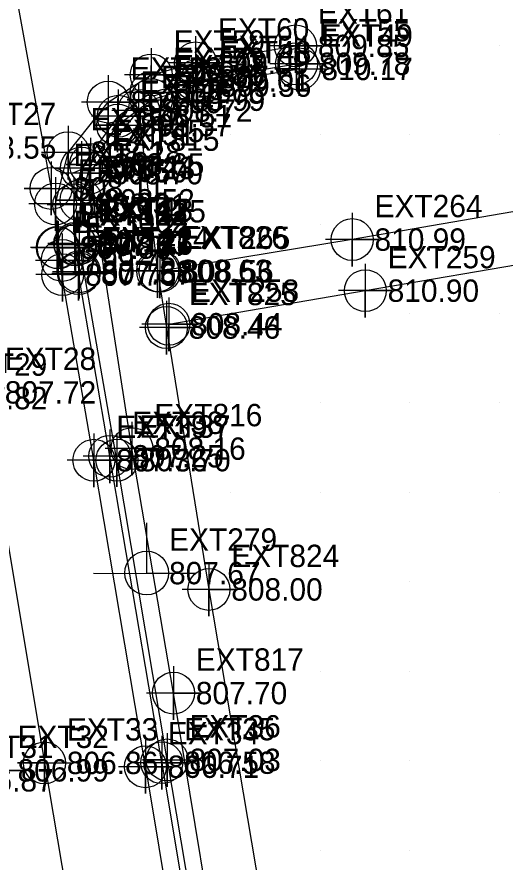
# Model space of a CAD drawing. Extents: x 1762120 to 1766775, y 709485 to 712965.
# Drawn here: x 1763846.1 to 1763900.7, y 712558.7 to 712653.2 of the extents above; entities that cross this region are included whole.
import ezdxf

# ---------------------------------------------------------------- set-up
doc = ezdxf.new("R2010")
doc.units = 0
for name, color, linetype in [('Exist DTM Crownline Cogo Elevation', 7, 'Continuous'), ('Exist DTM Crownline Cogo Number', 7, 'Continuous'), ('Exist DTM Crownline Cogo Point CELL', 7, 'Continuous'), ('Exist DTM Drainline', 7, 'Continuous'), ('Exist DTM Drainline Cogo Elevation', 7, 'Continuous'), ('Exist DTM Drainline Cogo Number', 7, 'Continuous'), ('Exist DTM Drainline Cogo Point CELL', 7, 'Continuous'), ('Exist DTM QL2 LIDAR Elevation Point', 7, 'Continuous'), ('Exist Roads Curbs', 7, 'Continuous'), ('Exist Roads Curbs Cogo Elevation', 7, 'Continuous'), ('Exist Roads Curbs Cogo Number', 7, 'Continuous'), ('Exist Roads Curbs Cogo Point CELL', 7, 'Continuous'), ('Exist Roads EOP', 7, 'Continuous'), ('Exist Roads EOP Cogo Elevation', 7, 'Continuous'), ('Exist Roads EOP Cogo Number', 7, 'Continuous'), ('Exist Roads EOP Cogo Point CELL', 7, 'Continuous'), ('Exist Roads EOP Other', 7, 'Continuous'), ('Exist Roads EOP Other Cogo Elevation', 7, 'Continuous'), ('Exist Roads EOP Other Cogo Number', 7, 'Continuous'), ('Exist Roads EOP Other Cogo Point CELL', 7, 'Continuous'), ('Exist Roads EOT', 7, 'Continuous'), ('Exist Roads EOT Cogo Comment', 7, 'Continuous'), ('Exist Roads EOT Cogo Elevation', 7, 'Continuous'), ('Exist Roads EOT Cogo Number', 7, 'Continuous'), ('Exist Roads EOT Cogo Point CELL', 7, 'Continuous'), ('Exist Structure Minor Drop Inlet', 7, 'Continuous'), ('Exist Structure Minor Drop Inlet Cogo Elevation', 7, 'Continuous'), ('Exist Structure Minor Drop Inlet Cogo Number', 7, 'Continuous'), ('Exist Structure Minor Drop Inlet Cogo Point CELL', 7, 'Continuous'), ('Exist Structure Minor Pipes RCP 15 Inch Cogo Elevation', 7, 'Continuous'), ('Exist Structure Minor Pipes RCP 15 Inch Cogo Number', 7, 'Continuous'), ('Exist Structure Minor Pipes RCP 15 Inch Cogo Point CELL', 7, 'Continuous'), ('Exist Utilities Power Joint Use Telephone CELL', 7, 'Continuous'), ('Exist Utilities Power Joint Use Telephone Cogo Elevation', 7, 'Continuous'), ('Exist Utilities Power Joint Use Telephone Cogo Number', 7, 'Continuous')]:
    doc.layers.add(name, color=color, linetype=linetype)

msp = doc.modelspace()

# ---------------------------------------------------------------- linework, layer by layer
at = {"layer": 'Exist DTM Crownline Cogo Point CELL'}
msp.add_lwpolyline([(1763843.626, 712571.925), (1763843.626, 712565.925), (1763843.626, 712568.925), (1763846.626, 712568.925), (1763840.626, 712568.925)], dxfattribs=at)
at = {"layer": 'Exist DTM Drainline'}
for points in [[(1763852.526, 712627.824), (1763852.422, 712632.146), (1763853.273, 712636.265), (1763857.393, 712642.054), (1763861.051, 712644.706), (1763866.138, 712646.042), (1763877.334, 712647.914)], [(1763862.254, 712569.784), (1763856.449, 712604.035), (1763852.957, 712624.458)], [(1763862.254, 712569.784), (1763865.235, 712551.849), (1763870.388, 712520.524), (1763872.037, 712510.908)]]:
    msp.add_lwpolyline(points, dxfattribs=at)
at = {"layer": 'Exist DTM Drainline Cogo Point CELL'}
for points in [[(1763877.334, 712650.914), (1763877.334, 712644.914), (1763877.334, 712647.914), (1763880.334, 712647.914), (1763874.334, 712647.914)], [(1763866.138, 712649.042), (1763866.138, 712643.042), (1763866.138, 712646.042), (1763869.138, 712646.042), (1763863.138, 712646.042)], [(1763861.051, 712647.706), (1763861.051, 712641.706), (1763861.051, 712644.706), (1763864.051, 712644.706), (1763858.051, 712644.706)], [(1763857.393, 712645.054), (1763857.393, 712639.054), (1763857.393, 712642.054), (1763860.393, 712642.054), (1763854.393, 712642.054)], [(1763853.273, 712639.265), (1763853.273, 712633.265), (1763853.273, 712636.265), (1763856.273, 712636.265), (1763850.273, 712636.265)], [(1763852.422, 712635.146), (1763852.422, 712629.146), (1763852.422, 712632.146), (1763855.422, 712632.146), (1763849.422, 712632.146)], [(1763852.526, 712630.824), (1763852.526, 712624.824), (1763852.526, 712627.824), (1763855.526, 712627.824), (1763849.526, 712627.824)], [(1763852.957, 712627.458), (1763852.957, 712621.458), (1763852.957, 712624.458), (1763855.957, 712624.458), (1763849.957, 712624.458)], [(1763856.449, 712607.035), (1763856.449, 712601.035), (1763856.449, 712604.035), (1763859.449, 712604.035), (1763853.449, 712604.035)], [(1763862.254, 712572.784), (1763862.254, 712566.784), (1763862.254, 712569.784), (1763865.254, 712569.784), (1763859.254, 712569.784)]]:
    msp.add_lwpolyline(points, dxfattribs=at)
for centre in [(1763877.334, 712647.914), (1763866.138, 712646.042), (1763861.051, 712644.706), (1763857.393, 712642.054), (1763853.273, 712636.265), (1763852.422, 712632.146), (1763852.526, 712627.824), (1763852.957, 712624.458), (1763856.449, 712604.035), (1763862.254, 712569.784)]:
    msp.add_circle(centre, 2.344, dxfattribs=at)
at = {"layer": 'Exist DTM QL2 LIDAR Elevation Point'}
for p, q in [((1763900, 712650), (1763900, 712650)), ((1763870, 712640), (1763870, 712640)), ((1763880, 712640), (1763880, 712640)), ((1763890, 712640), (1763890, 712640)), ((1763900, 712640), (1763900, 712640)), ((1763870, 712630), (1763870, 712630)), ((1763880, 712630), (1763880, 712630)), ((1763890, 712620), (1763890, 712620)), ((1763900, 712620), (1763900, 712620)), ((1763870, 712610), (1763870, 712610)), ((1763880, 712610), (1763880, 712610)), ((1763890, 712610), (1763890, 712610)), ((1763900, 712610), (1763900, 712610)), ((1763870, 712600), (1763870, 712600)), ((1763880, 712600), (1763880, 712600)), ((1763890, 712600), (1763890, 712600)), ((1763900, 712600), (1763900, 712600)), ((1763870, 712590), (1763870, 712590)), ((1763880, 712590), (1763880, 712590)), ((1763890, 712590), (1763890, 712590)), ((1763880, 712580), (1763880, 712580)), ((1763890, 712580), (1763890, 712580)), ((1763880, 712570), (1763880, 712570)), ((1763890, 712570), (1763890, 712570)), ((1763880, 712560), (1763880, 712560)), ((1763890, 712560), (1763890, 712560))]:
    msp.add_line(p, q, dxfattribs=at)
at = {"layer": 'Exist Roads Curbs'}
for points in [[(1763862.851, 712570.097), (1763857.241, 712603.606), (1763853.036, 712627.819), (1763853.222, 712632.652), (1763854.3, 712636.654), (1763857.323, 712641.052), (1763861.112, 712643.902), (1763866.262, 712645.471), (1763877.624, 712647.337)], [(1763862.851, 712570.097), (1763865.927, 712552.006), (1763871.153, 712520.608), (1763872.734, 712511.007)]]:
    msp.add_lwpolyline(points, dxfattribs=at)
at = {"layer": 'Exist Roads Curbs Cogo Point CELL'}
for points in [[(1763877.624, 712650.337), (1763877.624, 712644.337), (1763877.624, 712647.337), (1763874.894, 712647.337), (1763880.624, 712647.337)], [(1763866.262, 712648.471), (1763866.262, 712642.471), (1763866.262, 712645.471), (1763863.532, 712645.471), (1763869.262, 712645.471)], [(1763861.112, 712646.902), (1763861.112, 712640.902), (1763861.112, 712643.902), (1763858.382, 712643.902), (1763864.112, 712643.902)], [(1763857.323, 712644.052), (1763857.323, 712638.052), (1763857.323, 712641.052), (1763854.593, 712641.052), (1763860.323, 712641.052)], [(1763854.3, 712639.654), (1763854.3, 712633.654), (1763854.3, 712636.654), (1763851.57, 712636.654), (1763857.3, 712636.654)], [(1763853.222, 712635.652), (1763853.222, 712629.652), (1763853.222, 712632.652), (1763850.492, 712632.652), (1763856.222, 712632.652)], [(1763853.036, 712630.819), (1763853.036, 712624.819), (1763853.036, 712627.819), (1763850.306, 712627.819), (1763856.036, 712627.819)], [(1763857.241, 712606.606), (1763857.241, 712600.606), (1763857.241, 712603.606), (1763854.511, 712603.606), (1763860.241, 712603.606)], [(1763862.851, 712573.097), (1763862.851, 712567.097), (1763862.851, 712570.097), (1763860.121, 712570.097), (1763865.851, 712570.097)]]:
    msp.add_lwpolyline(points, dxfattribs=at)
for centre in [(1763877.624, 712647.337), (1763866.262, 712645.471), (1763861.112, 712643.902), (1763857.323, 712641.052), (1763854.3, 712636.654), (1763853.222, 712632.652), (1763853.036, 712627.819), (1763857.241, 712603.606), (1763862.851, 712570.097)]:
    msp.add_circle(centre, 2.344, dxfattribs=at)
at = {"layer": 'Exist Roads EOP'}
for points in [[(1763860.431, 712569.332), (1763854.67, 712603.593), (1763850.574, 712627.378), (1763850.38, 712632.243), (1763851.789, 712637.981), (1763856.271, 712643.636), (1763861.083, 712646.664), (1763866.035, 712648.008), (1763877.217, 712649.913)], [(1763860.431, 712569.332), (1763863.418, 712551.371), (1763868.592, 712520.228), (1763870.179, 712510.62)]]:
    msp.add_lwpolyline(points, dxfattribs=at)
at = {"layer": 'Exist Roads EOP Cogo Point CELL'}
for points in [[(1763877.217, 712652.913), (1763877.217, 712646.913), (1763877.217, 712649.913), (1763880.217, 712649.913), (1763874.217, 712649.913)], [(1763866.035, 712651.008), (1763866.035, 712645.008), (1763866.035, 712648.008), (1763869.035, 712648.008), (1763863.035, 712648.008)], [(1763861.083, 712649.664), (1763861.083, 712643.664), (1763861.083, 712646.664), (1763864.083, 712646.664), (1763858.083, 712646.664)], [(1763856.271, 712646.636), (1763856.271, 712640.636), (1763856.271, 712643.636), (1763859.271, 712643.636), (1763853.271, 712643.636)], [(1763851.789, 712640.981), (1763851.789, 712634.981), (1763851.789, 712637.981), (1763854.789, 712637.981), (1763848.789, 712637.981)], [(1763850.38, 712635.243), (1763850.38, 712629.243), (1763850.38, 712632.243), (1763853.38, 712632.243), (1763847.38, 712632.243)], [(1763850.574, 712630.378), (1763850.574, 712624.378), (1763850.574, 712627.378), (1763853.574, 712627.378), (1763847.574, 712627.378)], [(1763854.67, 712606.593), (1763854.67, 712600.593), (1763854.67, 712603.593), (1763857.67, 712603.593), (1763851.67, 712603.593)], [(1763860.431, 712572.332), (1763860.431, 712566.332), (1763860.431, 712569.332), (1763863.431, 712569.332), (1763857.431, 712569.332)]]:
    msp.add_lwpolyline(points, dxfattribs=at)
for centre in [(1763877.217, 712649.913), (1763866.035, 712648.008), (1763861.083, 712646.664), (1763856.271, 712643.636), (1763851.789, 712637.981), (1763850.38, 712632.243), (1763850.574, 712627.378), (1763854.67, 712603.593), (1763860.431, 712569.332)]:
    msp.add_circle(centre, 2.344, dxfattribs=at)
at = {"layer": 'Exist Roads EOP Other'}
msp.add_lwpolyline([(1763854.132, 712635.686), (1763859.673, 712642.69), (1763861.796, 712624.763), (1763862.778, 712618.431), (1763867.533, 712589.151), (1763873.757, 712552.303), (1763879.823, 712515.119), (1763886.226, 712476.795), (1763880.517, 712475.736), (1763875.337, 712505.878), (1763869.64, 712540.755), (1763863.568, 712577.565), (1763858.925, 712604.892)], close=True, dxfattribs=at)
for points in [[(1763928.955, 712636.103), (1763903.68, 712631.732), (1763883.556, 712628.264), (1763862.046, 712624.714)], [(1763863.043, 712618.801), (1763885.025, 712622.553), (1763905.122, 712625.986), (1763930.142, 712630.358)]]:
    msp.add_lwpolyline(points, dxfattribs=at)
at = {"layer": 'Exist Roads EOP Other Cogo Point CELL'}
for points in [[(1763859.673, 712645.69), (1763859.673, 712639.69), (1763859.673, 712642.69), (1763862.673, 712642.69), (1763856.673, 712642.69)], [(1763854.132, 712638.686), (1763854.132, 712632.686), (1763854.132, 712635.686), (1763857.132, 712635.686), (1763851.132, 712635.686)], [(1763883.556, 712631.264), (1763883.556, 712625.264), (1763883.556, 712628.264), (1763886.556, 712628.264), (1763880.556, 712628.264)], [(1763861.796, 712627.763), (1763861.796, 712621.763), (1763861.796, 712624.763), (1763864.796, 712624.763), (1763858.796, 712624.763)], [(1763862.046, 712627.714), (1763862.046, 712621.714), (1763862.046, 712624.714), (1763865.046, 712624.714), (1763859.046, 712624.714)], [(1763885.025, 712625.553), (1763885.025, 712619.553), (1763885.025, 712622.553), (1763888.025, 712622.553), (1763882.025, 712622.553)], [(1763862.778, 712621.431), (1763862.778, 712615.431), (1763862.778, 712618.431), (1763865.778, 712618.431), (1763859.778, 712618.431)], [(1763863.043, 712621.801), (1763863.043, 712615.801), (1763863.043, 712618.801), (1763866.043, 712618.801), (1763860.043, 712618.801)], [(1763858.925, 712607.892), (1763858.925, 712601.892), (1763858.925, 712604.892), (1763861.925, 712604.892), (1763855.925, 712604.892)], [(1763867.533, 712592.151), (1763867.533, 712586.151), (1763867.533, 712589.151), (1763870.533, 712589.151), (1763864.533, 712589.151)], [(1763863.568, 712580.565), (1763863.568, 712574.565), (1763863.568, 712577.565), (1763866.568, 712577.565), (1763860.568, 712577.565)]]:
    msp.add_lwpolyline(points, dxfattribs=at)
for centre in [(1763859.673, 712642.69), (1763854.132, 712635.686), (1763883.556, 712628.264), (1763861.796, 712624.763), (1763862.046, 712624.714), (1763885.025, 712622.553), (1763862.778, 712618.431), (1763863.043, 712618.801), (1763858.925, 712604.892), (1763867.533, 712589.151), (1763863.568, 712577.565)]:
    msp.add_circle(centre, 2.344, dxfattribs=at)
at = {"layer": 'Exist Roads EOT'}
msp.add_line((1763842.863, 712672.898), (1763849.88, 712633.986), dxfattribs=at)
for points in [[(1763789.832, 712926.884), (1763795.992, 712888.052), (1763800.75, 712859.942), (1763807.254, 712820.955), (1763816.86, 712762.721), (1763822.148, 712731.849), (1763825.695, 712709.767), (1763831.213, 712676.817), (1763837.744, 712638.56), (1763842.2, 712611.183), (1763849.139, 712569.759)], [(1763849.139, 712569.759), (1763854.496, 712537.963), (1763859.372, 712509.363)]]:
    msp.add_lwpolyline(points, dxfattribs=at)
at = {"layer": 'Exist Roads EOT Cogo Point CELL'}
for points in [[(1763849.88, 712636.986), (1763849.88, 712630.986), (1763849.88, 712633.986), (1763846.88, 712633.986), (1763852.88, 712633.986)], [(1763849.139, 712572.759), (1763849.139, 712566.759), (1763849.139, 712569.759), (1763846.139, 712569.759), (1763852.139, 712569.759)]]:
    msp.add_lwpolyline(points, dxfattribs=at)
for centre in [(1763849.88, 712633.986), (1763849.139, 712569.759)]:
    msp.add_circle(centre, 2.344, dxfattribs=at)
at = {"layer": 'Exist Structure Minor Drop Inlet'}
msp.add_lwpolyline([(1763850.681, 712627.337), (1763851.172, 712624.343), (1763853.028, 712624.663), (1763852.61, 712627.677)], dxfattribs=at)
at = {"layer": 'Exist Structure Minor Drop Inlet Cogo Point CELL'}
for points in [[(1763850.681, 712630.337), (1763850.681, 712624.337), (1763850.681, 712627.337), (1763853.681, 712627.337), (1763847.681, 712627.337)], [(1763852.61, 712630.677), (1763852.61, 712624.677), (1763852.61, 712627.677), (1763855.61, 712627.677), (1763849.61, 712627.677)], [(1763851.172, 712627.343), (1763851.172, 712621.343), (1763851.172, 712624.343), (1763854.172, 712624.343), (1763848.172, 712624.343)], [(1763853.028, 712627.663), (1763853.028, 712621.663), (1763853.028, 712624.663), (1763856.028, 712624.663), (1763850.028, 712624.663)]]:
    msp.add_lwpolyline(points, dxfattribs=at)
for centre in [(1763852.61, 712627.677), (1763850.681, 712627.337), (1763853.028, 712624.663), (1763851.172, 712624.343)]:
    msp.add_circle(centre, 2.344, dxfattribs=at)
at = {"layer": 'Exist Structure Minor Pipes RCP 15 Inch Cogo Point CELL'}
msp.add_lwpolyline([(1763851.128, 712628.938), (1763851.128, 712622.938), (1763851.128, 712625.938), (1763854.128, 712625.938), (1763848.128, 712625.938)], dxfattribs=at)
msp.add_circle((1763851.128, 712625.938), 2.344, dxfattribs=at)
at = {"layer": 'Exist Utilities Power Joint Use Telephone CELL'}
msp.add_line((1763860.578, 712590.978), (1763860.578, 712590.978), dxfattribs=at)
msp.add_lwpolyline([(1763854.64, 712590.978), (1763865.978, 712590.94), (1763860.578, 712590.958), (1763860.578, 712596.603)], dxfattribs=at)
msp.add_circle((1763860.579, 712590.984), 2.45, dxfattribs=at)

# ---------------------------------------------------------------- texts
at = {"layer": 'Exist DTM Crownline Cogo Elevation'}
for s, p in [('807.82', (1763839.233, 712609.29)), ('806.99', (1763846.126, 712567.675))]:
    msp.add_text(s, height=2.5, dxfattribs=at).set_placement(p)
at = {"layer": 'Exist DTM Crownline Cogo Number'}
for s, p in [('EXT29', (1763839.233, 712613.04)), ('EXT32', (1763846.126, 712571.425))]:
    msp.add_text(s, height=2.5, dxfattribs=at).set_placement(p)
at = {"layer": 'Exist DTM Drainline Cogo Elevation'}
for s, p in [('809.78', (1763879.834, 712646.664)), ('809.01', (1763868.638, 712644.792)), ('808.75', (1763863.551, 712643.456)), ('808.51', (1763859.893, 712640.804)), ('808.23', (1763855.773, 712635.015)), ('808.01', (1763854.922, 712630.896)), ('807.63', (1763855.026, 712626.574)), ('807.57', (1763855.457, 712623.208)), ('807.25', (1763858.949, 712602.785)), ('806.58', (1763864.754, 712568.534))]:
    msp.add_text(s, height=2.5, dxfattribs=at).set_placement(p)
at = {"layer": 'Exist DTM Drainline Cogo Number'}
for s, p in [('EXT55', (1763879.834, 712650.414)), ('EXT54', (1763868.638, 712648.542)), ('EXT53', (1763863.551, 712647.206)), ('EXT52', (1763859.893, 712644.554)), ('EXT51', (1763855.773, 712638.765)), ('EXT50', (1763854.922, 712634.646)), ('EXT42', (1763855.026, 712630.324)), ('EXT41', (1763855.457, 712626.958)), ('EXT38', (1763858.949, 712606.535)), ('EXT35', (1763864.754, 712572.284))]:
    msp.add_text(s, height=2.5, dxfattribs=at).set_placement(p)
at = {"layer": 'Exist Roads Curbs Cogo Elevation'}
for s, p in [('810.17', (1763880.124, 712646.087)), ('809.36', (1763868.762, 712644.221)), ('808.99', (1763863.612, 712642.652)), ('808.57', (1763859.823, 712639.802)), ('808.65', (1763856.8, 712635.404)), ('808.52', (1763855.722, 712631.402)), ('808.26', (1763855.536, 712626.569)), ('807.70', (1763859.741, 712602.356)), ('807.03', (1763865.351, 712568.847))]:
    msp.add_text(s, height=2.5, dxfattribs=at).set_placement(p)
at = {"layer": 'Exist Roads Curbs Cogo Number'}
for s, p in [('EXT49', (1763880.124, 712649.837)), ('EXT48', (1763868.762, 712647.971)), ('EXT47', (1763863.612, 712646.402)), ('EXT46', (1763859.823, 712643.552)), ('EXT45', (1763856.8, 712639.154)), ('EXT44', (1763855.722, 712635.152)), ('EXT43', (1763855.536, 712630.319)), ('EXT37', (1763859.741, 712606.106)), ('EXT36', (1763865.351, 712572.597))]:
    msp.add_text(s, height=2.5, dxfattribs=at).set_placement(p)
at = {"layer": 'Exist Roads EOP Cogo Elevation'}
for s, p in [('809.85', (1763879.717, 712648.663)), ('809.09', (1763868.535, 712646.758)), ('808.86', (1763863.583, 712645.414)), ('808.50', (1763858.771, 712642.386)), ('808.18', (1763854.289, 712636.731)), ('808.03', (1763852.88, 712630.993)), ('807.87', (1763853.074, 712626.128)), ('807.36', (1763857.17, 712602.343)), ('806.71', (1763862.931, 712568.082))]:
    msp.add_text(s, height=2.5, dxfattribs=at).set_placement(p)
at = {"layer": 'Exist Roads EOP Cogo Number'}
for s, p in [('EXT61', (1763879.717, 712652.413)), ('EXT60', (1763868.535, 712650.508)), ('EXT59', (1763863.583, 712649.164)), ('EXT58', (1763858.771, 712646.136)), ('EXT57', (1763854.289, 712640.481)), ('EXT56', (1763852.88, 712634.743)), ('EXT40', (1763853.074, 712629.878)), ('EXT39', (1763857.17, 712606.093)), ('EXT34', (1763862.931, 712571.832))]:
    msp.add_text(s, height=2.5, dxfattribs=at).set_placement(p)
at = {"layer": 'Exist Roads EOP Other Cogo Elevation'}
for s, p in [('808.72', (1763862.173, 712641.44)), ('808.70', (1763856.632, 712634.436)), ('810.99', (1763886.056, 712627.014)), ('808.63', (1763864.296, 712623.513)), ('808.56', (1763864.546, 712623.464)), ('810.90', (1763887.525, 712621.303)), ('808.46', (1763865.278, 712617.181)), ('808.44', (1763865.543, 712617.551)), ('808.16', (1763861.425, 712603.642)), ('808.00', (1763870.033, 712587.901)), ('807.70', (1763866.068, 712576.315))]:
    msp.add_text(s, height=2.5, dxfattribs=at).set_placement(p)
at = {"layer": 'Exist Roads EOP Other Cogo Number'}
for s, p in [('EXT827', (1763862.173, 712645.19)), ('EXT815', (1763856.632, 712638.186)), ('EXT264', (1763886.056, 712630.764)), ('EXT826', (1763864.296, 712627.263)), ('EXT265', (1763864.546, 712627.214)), ('EXT259', (1763887.525, 712625.053)), ('EXT825', (1763865.278, 712620.931)), ('EXT258', (1763865.543, 712621.301)), ('EXT816', (1763861.425, 712607.392)), ('EXT824', (1763870.033, 712591.651)), ('EXT817', (1763866.068, 712580.065))]:
    msp.add_text(s, height=2.5, dxfattribs=at).set_placement(p)
at = {"layer": 'Exist Roads EOT Cogo Comment'}
msp.add_text('BL*3002', height=2.5, dxfattribs=at).set_placement((1763852.38, 712628.986))
at = {"layer": 'Exist Roads EOT Cogo Elevation'}
for s, p in [('808.55', (1763840.244, 712637.31)), ('808.11', (1763852.38, 712632.736)), ('807.72', (1763844.7, 712609.933)), ('806.86', (1763851.639, 712568.509)), ('806.87', (1763839.941, 712566.56))]:
    msp.add_text(s, height=2.5, dxfattribs=at).set_placement(p)
at = {"layer": 'Exist Roads EOT Cogo Number'}
for s, p in [('EXT27', (1763840.244, 712641.06)), ('EXT62', (1763852.38, 712636.486)), ('EXT28', (1763844.7, 712613.683)), ('EXT33', (1763851.639, 712572.259)), ('EXT31', (1763839.941, 712570.31))]:
    msp.add_text(s, height=2.5, dxfattribs=at).set_placement(p)
at = {"layer": 'Exist Structure Minor Drop Inlet Cogo Elevation'}
for s, p in [('807.57', (1763855.11, 712626.427)), ('807.79', (1763853.181, 712626.087)), ('807.76', (1763853.672, 712623.093)), ('807.58', (1763855.528, 712623.413))]:
    msp.add_text(s, height=2.5, dxfattribs=at).set_placement(p)
at = {"layer": 'Exist Structure Minor Drop Inlet Cogo Number'}
for s, p in [('EXT125', (1763855.11, 712630.177)), ('EXT122', (1763853.181, 712629.837)), ('EXT123', (1763853.672, 712626.843)), ('EXT124', (1763855.528, 712627.163))]:
    msp.add_text(s, height=2.5, dxfattribs=at).set_placement(p)
at = {"layer": 'Exist Structure Minor Pipes RCP 15 Inch Cogo Elevation'}
msp.add_text('799.75', height=2.5, dxfattribs=at).set_placement((1763853.628, 712624.688))
at = {"layer": 'Exist Structure Minor Pipes RCP 15 Inch Cogo Number'}
msp.add_text('EXT121', height=2.5, dxfattribs=at).set_placement((1763853.628, 712628.438))
at = {"layer": 'Exist Utilities Power Joint Use Telephone Cogo Elevation'}
msp.add_text('807.67', height=2.5, dxfattribs=at).set_placement((1763863.078, 712589.728))
at = {"layer": 'Exist Utilities Power Joint Use Telephone Cogo Number'}
msp.add_text('EXT279', height=2.5, dxfattribs=at).set_placement((1763863.078, 712593.478))

doc.saveas('drawing.dxf')
